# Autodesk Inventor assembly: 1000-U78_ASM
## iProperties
Created: 2006-10
Part Number: 1000-U78_ASM
Document SubType Name: Assembly
Designer: Andy Moles
Translation Standard: STEP AP203
File Name: 1000-U78_ASM
Preprocessor: PRO/ENGINEER BY PARAMETRIC TECHNOLOGY CORPORATION, 2001390
Postprocessor: Build: 243, Release: 10 SP1 - Date: Mon 06/06/2005
Sent Units: MILLIMETERS
Uncertainty: 0.0061212255527759996
Author: Andy Moles
